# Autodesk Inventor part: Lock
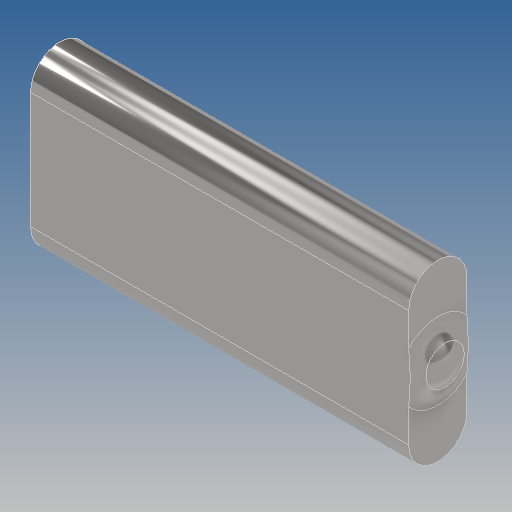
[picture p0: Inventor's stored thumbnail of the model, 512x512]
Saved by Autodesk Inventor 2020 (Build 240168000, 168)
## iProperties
Created: 2019-10
Part Number: Lock
Material: Generic
Document SubType Name: Modeling
Designer: yello
Density: 1 g/cm^3
Appearance: Default
Author: yello
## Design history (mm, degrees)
sketch "Sketch1"
  geometry: L1 (0, 0)-(4, 0); L2 (0, -1)-(4, -1); L3 (4, 1)-(0, 1); A1 r 1 centre (0, 0) between (0, 1) and (0, -1); A2 r 1 centre (4, 0) between (4, -1) and (4, 1); 1 further point
  constraints: 8 end point, 4 point on circle, 4 tangent, 2 centre point, 1 horizontal, 1 midpoint, 1 parallel
  dimensions: "d0" = 4 distance of L1.start L1.end; "d1" = 2 diameter of A2
extrude "Extrusion1" new body sketch "Sketch1" distance "d2" = 13; taper "d3" = 0 deg
workplane "Work Plane1"
sketch "Sketch3"
  geometry: L1 (0, 4)-(0, 0); C1 r 1 at (0, 2); C2 r 1 at (0, 2); A1 r 1 centre (0, 4) between (1, 4) and (-1, 4); A2 r 1 centre (0, 0) between (-1, 0) and (1, 0); 3 further points
  constraints: 4 centre point, 4 point on circle, 2 end point, 1 coincident
  dimensions: "d6" = 2 diameter of C2
revolve "Revolution1" sketch "Sketch3" stored, may be unused: angle "d7" = 90 deg
fillet "Fillet1" dims "d8" = 1
body "Solid1"
other parameters: "d5" = -0.5
